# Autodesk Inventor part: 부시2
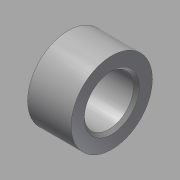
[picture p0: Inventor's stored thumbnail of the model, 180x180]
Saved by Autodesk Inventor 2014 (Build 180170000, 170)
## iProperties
Created: 2015-09
Part Number: 부시2
Material: 강철, 연강
Document SubType Name: Modeling
Designer: mduedu
Density: 7.86 g/cm^3
Description: 외주 가공
Mass: 45.4 g
Surface Area: 28.3815 cm^2
Volume: 5.77608 cm^3
Appearance: 강철
Author: mduedu
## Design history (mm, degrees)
sketch "스케치1"
  geometry: C1 r 14 at (0, 0); C2 r 8.5 at (0, 0); 1 further point
  constraints: 2 centre point, 2 coincident
  dimensions: "d0" = 28 diameter of C1; "d2" = 17 diameter of C2
extrude "돌출1" new body sketch "스케치1" distance "d3" = 15; taper "d4" = 0 deg
chamfer "모따기1" distance "d5" = 1; stored, may be unused: second distance "d6" = 2, angle "d7" = 45 deg
node "솔리드1"
